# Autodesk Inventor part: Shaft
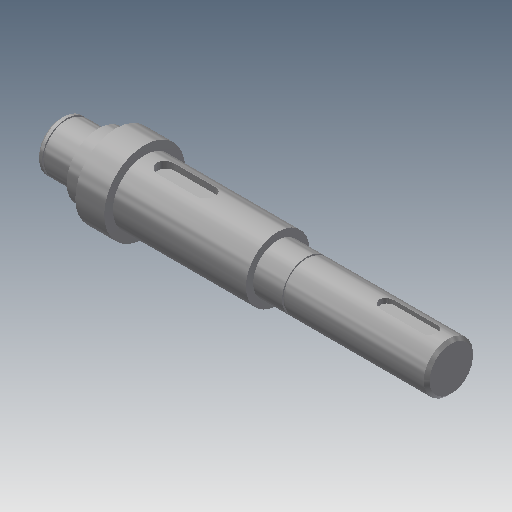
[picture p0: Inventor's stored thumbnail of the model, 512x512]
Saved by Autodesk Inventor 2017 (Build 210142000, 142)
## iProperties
Created: 2019-02
Part Number: Shaft
Material: Steel
Document SubType Name: Modeling
Designer: user
Density: 7.85 g/cm^3
Appearance: Steel
Mass: 329.535 g
Surface Area: 97.9427 cm^2
Volume: 41.979 cm^3
CustomPartVersion: 1
Author: user
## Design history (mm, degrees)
sketch "Main Sketch"
  geometry: L1 (0, 0)-(135, 0) reference; L2 (0, 0)-(0, 8.5); L3 (0, 8.5)-(13, 8.5); L4 (13, 8.5)-(13, 11); L5 (13, 11)-(19, 11); L6 (19, 11)-(19, 14); L7 (29, 14)-(29, 11); L8 (19, 14)-(29, 14); L9 (75, 11)-(75, 8.5); L10 (29, 11)-(75, 11); L11 (135, 8.5)-(135, 0); L12 (75, 8.5)-(135, 8.5)
  constraints: 24 end point, 6 vertical, 1 horizontal
  dimensions: "d3" = 17 diameter of L3 L1 (derived); "d4" = 22 diameter of L5 L1 (derived); "d5" = 28 diameter of L8 L1 (derived); "d6" = 22 diameter of L10 L1 (derived); "d7" = 17 diameter of L12 L1 (derived)
revolve "Revolution1" sketch "Main Sketch" stored, may be unused: angle "d8" = 0 deg
node "Keyway1"
node "Keyway2"
chamfer "Chamfer3" distance "d15" = 1; stored, may be unused: second distance "d16" = 0.125, angle "d17" = 45 deg
node "Retaining Ring Groove1"
chamfer "Chamfer2" distance "d12" = 1; stored, may be unused: second distance "d13" = 0.125, angle "d14" = 45 deg
node "Retaining Ring Groove2"
body "Solid1"
feature "iFeature27:1"
feature "iFeature27:2"
feature "iFeature3:1"
feature "iFeature3:2"
other parameters: "d0" = 0, "d1" = 0, "d2" = 0
